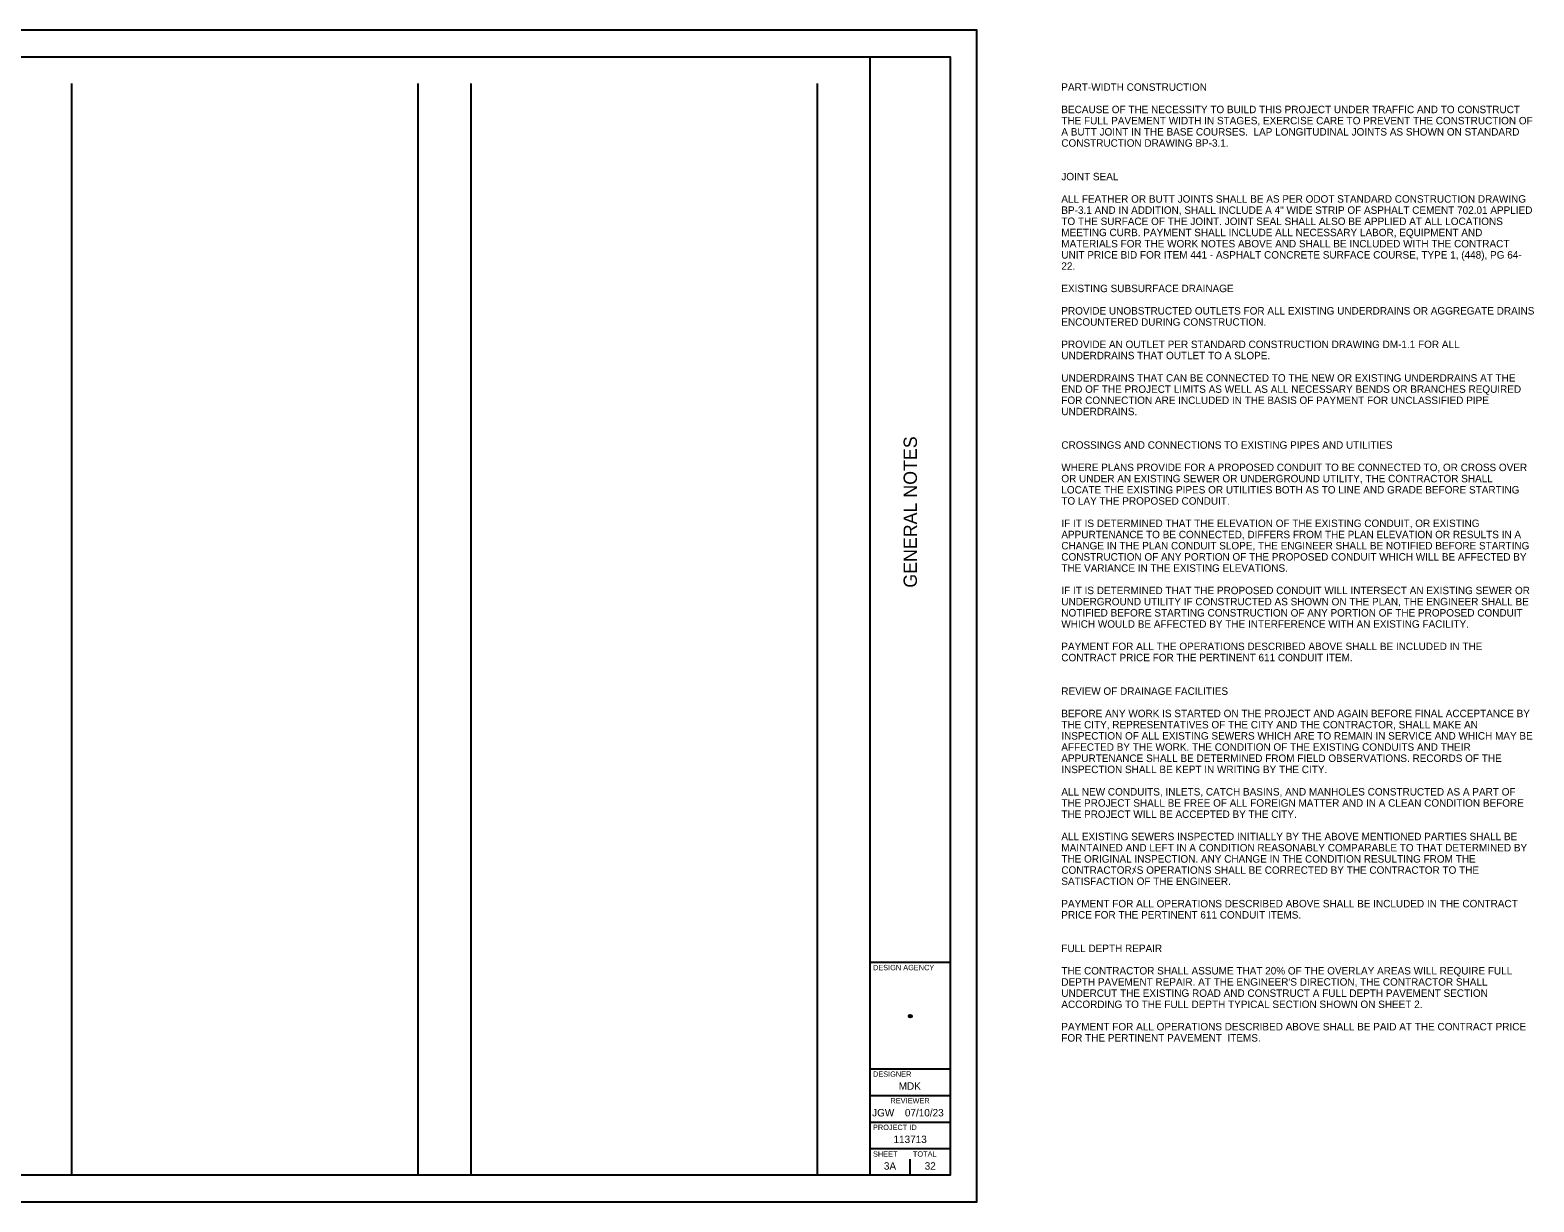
# Model space of a CAD drawing. Extents: x -8.5 to 44.5, y -30.9 to 22.
# Drawn here: x 16.22 to 44.46, y 0 to 22 of the extents above; entities that cross this region are included whole.
import ezdxf

# ---------------------------------------------------------------- set-up
doc = ezdxf.new("R2010")
doc.units = 0
for name, color, linetype in [('Default', 7, 'Continuous'), ('SN_X_Public', 7, 'Continuous'), ('SV_P_Mon_Cells_Set', 7, 'Continuous'), ('SV_X_Mon_Cells_Found', 7, 'Continuous'), ('SV_X_Random_Point', 7, 'Continuous'), ('SV_X_Shot_Marker', 7, 'Continuous')]:
    doc.layers.add(name, color=color, linetype=linetype)

msp = doc.modelspace()

# ---------------------------------------------------------------- linework, layer by layer
at = {"layer": 'Default'}
for p, q in [((32.724, 3.488), (32.776, 3.488)), ((32.75, 3.488), (32.799, 3.488))]:
    msp.add_line(p, q, dxfattribs=at)
msp.add_circle((32.75, 3.488), 0.026, dxfattribs=at)
at = {"layer": 'SN_X_Public'}
for p, q in [((17, 21), (17, 0.5)), ((23.5, 21), (23.5, 0.5)), ((24.5, 21), (24.5, 0.5)), ((31, 21), (31, 0.5))]:
    msp.add_line(p, q, dxfattribs=at)
at = {"layer": 'SV_P_Mon_Cells_Set'}
msp.add_lwpolyline([(0, 0), (34, 0), (34, 22), (0, 22)], close=True, dxfattribs=at)
at = {"layer": 'SV_X_Mon_Cells_Found'}
for p, q in [((32, 0.5), (32, 21.5)), ((32, 4.5), (33.5, 4.5)), ((32, 2.5), (33.5, 2.5)), ((32, 2), (33.5, 2)), ((32, 1.5), (33.5, 1.5)), ((32, 1), (33.5, 1))]:
    msp.add_line(p, q, dxfattribs=at)
msp.add_lwpolyline([(1.5, 21.5), (33.5, 21.5), (33.5, 0.5), (1.5, 0.5)], close=True, dxfattribs=at)
at = {"layer": 'SV_X_Shot_Marker'}
for p, q in [((32.75, 3.5), (32.75, 3.5)), ((32.375, 0.675), (32.375, 0.675)), ((32.75, 0.5), (32.75, 0.8))]:
    msp.add_line(p, q, dxfattribs=at)

# ---------------------------------------------------------------- texts
at = {"layer": 'Default'}
for s, p in [('3A', (32.747, 3.478)), ('1', (32.749, 3.495)), ('Drawing', (32.782, 3.495)), ('1:1', (32.782, 3.478))]:
    msp.add_text(s, height=0.00328, dxfattribs=at).set_placement(p)
at = {"layer": 'SV_X_Random_Point'}
for s, p in [('PART-WIDTH CONSTRUCTION', (35.587, 20.86)), ('THE FULL PAVEMENT WIDTH IN STAGES, EXERCISE CARE TO PREVENT THE CONSTRUCTION OF ', (35.587, 20.23)), ('BECAUSE OF THE NECESSITY TO BUILD THIS PROJECT UNDER TRAFFIC AND TO CONSTRUCT ', (35.587, 20.44)), ('A BUTT JOINT IN THE BASE COURSES.  LAP LONGITUDINAL JOINTS AS SHOWN ON STANDARD ', (35.587, 20.02)), ('CONSTRUCTION DRAWING BP-3.1.', (35.587, 19.81)), ('JOINT SEAL', (35.587, 19.18)), ('ALL FEATHER OR BUTT JOINTS SHALL BE AS PER ODOT STANDARD CONSTRUCTION DRAWING ', (35.587, 18.76)), ('BP-3.1 AND IN ADDITION, SHALL INCLUDE A 4" WIDE STRIP OF ASPHALT CEMENT 702.01 APPLIED ', (35.587, 18.55)), ('TO THE SURFACE OF THE JOINT. JOINT SEAL SHALL ALSO BE APPLIED AT ALL LOCATIONS ', (35.587, 18.34)), ('MEETING CURB. PAYMENT SHALL INCLUDE ALL NECESSARY LABOR, EQUIPMENT AND ', (35.587, 18.13)), ('UNIT PRICE BID FOR ITEM 441 - ASPHALT CONCRETE SURFACE COURSE, TYPE 1, (448), PG 64-', (35.587, 17.71)), ('MATERIALS FOR THE WORK NOTES ABOVE AND SHALL BE INCLUDED WITH THE CONTRACT ', (35.587, 17.92)), ('22.', (35.587, 17.5)), ('EXISTING SUBSURFACE DRAINAGE', (35.587, 17.08)), ('PROVIDE UNOBSTRUCTED OUTLETS FOR ALL EXISTING UNDERDRAINS OR AGGREGATE DRAINS ', (35.587, 16.66)), ('ENCOUNTERED DURING CONSTRUCTION.', (35.587, 16.45)), ('PROVIDE AN OUTLET PER STANDARD CONSTRUCTION DRAWING DM-1.1 FOR ALL ', (35.587, 16.03)), ('UNDERDRAINS THAT OUTLET TO A SLOPE.', (35.587, 15.82)), ('UNDERDRAINS THAT CAN BE CONNECTED TO THE NEW OR EXISTING UNDERDRAINS AT THE ', (35.587, 15.4)), ('END OF THE PROJECT LIMITS AS WELL AS ALL NECESSARY BENDS OR BRANCHES REQUIRED ', (35.587, 15.19)), ('FOR CONNECTION ARE INCLUDED IN THE BASIS OF PAYMENT FOR UNCLASSIFIED PIPE ', (35.587, 14.98)), ('UNDERDRAINS.', (35.587, 14.77)), ('CROSSINGS AND CONNECTIONS TO EXISTING PIPES AND UTILITIES', (35.587, 14.14)), ('WHERE PLANS PROVIDE FOR A PROPOSED CONDUIT TO BE CONNECTED TO, OR CROSS OVER ', (35.587, 13.72)), ('OR UNDER AN EXISTING SEWER OR UNDERGROUND UTILITY, THE CONTRACTOR SHALL ', (35.587, 13.51)), ('LOCATE THE EXISTING PIPES OR UTILITIES BOTH AS TO LINE AND GRADE BEFORE STARTING ', (35.587, 13.3)), ('TO LAY THE PROPOSED CONDUIT.', (35.587, 13.09)), ('IF IT IS DETERMINED THAT THE ELEVATION OF THE EXISTING CONDUIT, OR EXISTING ', (35.587, 12.67)), ('APPURTENANCE TO BE CONNECTED, DIFFERS FROM THE PLAN ELEVATION OR RESULTS IN A ', (35.587, 12.46)), ('CHANGE IN THE PLAN CONDUIT SLOPE, THE ENGINEER SHALL BE NOTIFIED BEFORE STARTING ', (35.587, 12.25)), ('CONSTRUCTION OF ANY PORTION OF THE PROPOSED CONDUIT WHICH WILL BE AFFECTED BY ', (35.587, 12.04)), ('THE VARIANCE IN THE EXISTING ELEVATIONS.', (35.587, 11.83)), ('UNDERGROUND UTILITY IF CONSTRUCTED AS SHOWN ON THE PLAN, THE ENGINEER SHALL BE ', (35.587, 11.2)), ('IF IT IS DETERMINED THAT THE PROPOSED CONDUIT WILL INTERSECT AN EXISTING SEWER OR ', (35.587, 11.41)), ('NOTIFIED BEFORE STARTING CONSTRUCTION OF ANY PORTION OF THE PROPOSED CONDUIT ', (35.587, 10.99)), ('WHICH WOULD BE AFFECTED BY THE INTERFERENCE WITH AN EXISTING FACILITY.', (35.587, 10.78)), ('PAYMENT FOR ALL THE OPERATIONS DESCRIBED ABOVE SHALL BE INCLUDED IN THE ', (35.587, 10.36)), ('CONTRACT PRICE FOR THE PERTINENT 611 CONDUIT ITEM.', (35.587, 10.15)), ('REVIEW OF DRAINAGE FACILITIES', (35.587, 9.52)), ('BEFORE ANY WORK IS STARTED ON THE PROJECT AND AGAIN BEFORE FINAL ACCEPTANCE BY ', (35.587, 9.1)), ('THE CITY, REPRESENTATIVES OF THE CITY AND THE CONTRACTOR, SHALL MAKE AN ', (35.587, 8.89)), ('INSPECTION OF ALL EXISTING SEWERS WHICH ARE TO REMAIN IN SERVICE AND WHICH MAY BE ', (35.587, 8.68)), ('AFFECTED BY THE WORK. THE CONDITION OF THE EXISTING CONDUITS AND THEIR ', (35.587, 8.47)), ('APPURTENANCE SHALL BE DETERMINED FROM FIELD OBSERVATIONS. RECORDS OF THE ', (35.587, 8.26)), ('INSPECTION SHALL BE KEPT IN WRITING BY THE CITY.', (35.587, 8.05)), ('ALL NEW CONDUITS, INLETS, CATCH BASINS, AND MANHOLES CONSTRUCTED AS A PART OF ', (35.587, 7.63)), ('THE PROJECT SHALL BE FREE OF ALL FOREIGN MATTER AND IN A CLEAN CONDITION BEFORE ', (35.587, 7.42)), ('THE PROJECT WILL BE ACCEPTED BY THE CITY.', (35.587, 7.21)), ('ALL EXISTING SEWERS INSPECTED INITIALLY BY THE ABOVE MENTIONED PARTIES SHALL BE ', (35.587, 6.79)), ('THE ORIGINAL INSPECTION. ANY CHANGE IN THE CONDITION RESULTING FROM THE ', (35.587, 6.37)), ('MAINTAINED AND LEFT IN A CONDITION REASONABLY COMPARABLE TO THAT DETERMINED BY ', (35.587, 6.58)), ('CONTRACTORﾒS OPERATIONS SHALL BE CORRECTED BY THE CONTRACTOR TO THE ', (35.587, 6.16)), ('SATISFACTION OF THE ENGINEER.', (35.587, 5.95)), ('PAYMENT FOR ALL OPERATIONS DESCRIBED ABOVE SHALL BE INCLUDED IN THE CONTRACT ', (35.587, 5.53)), ('PRICE FOR THE PERTINENT 611 CONDUIT ITEMS.', (35.587, 5.32)), ('FULL DEPTH REPAIR', (35.587, 4.69)), ('THE CONTRACTOR SHALL ASSUME THAT 20% OF THE OVERLAY AREAS WILL REQUIRE FULL ', (35.587, 4.27)), ('UNDERCUT THE EXISTING ROAD AND CONSTRUCT A FULL DEPTH PAVEMENT SECTION ', (35.587, 3.85)), ("DEPTH PAVEMENT REPAIR. AT THE ENGINEER'S DIRECTION, THE CONTRACTOR SHALL ", (35.587, 4.06)), ('ACCORDING TO THE FULL DEPTH TYPICAL SECTION SHOWN ON SHEET 2.', (35.587, 3.64)), ('PAYMENT FOR ALL OPERATIONS DESCRIBED ABOVE SHALL BE PAID AT THE CONTRACT PRICE ', (35.587, 3.22)), ('FOR THE PERTINENT PAVEMENT  ITEMS.', (35.587, 3.01))]:
    msp.add_text(s, height=0.14, dxfattribs=at).set_placement(p)
at = {"layer": 'SV_X_Shot_Marker'}
msp.add_text('GENERAL NOTES', height=0.25, rotation=90, dxfattribs=at).set_placement((32.875, 11.531))
for s, height, p in [('DESIGN AGENCY', 0.1, (32.05, 4.35)), ('DESIGNER', 0.1, (32.05, 2.35)), ('MDK', 0.14, (32.533, 2.105)), ('JGW', 0.14, (32.034, 1.605)), ('REVIEWER', 0.1, (32.378, 1.85)), ('07/10/23', 0.14, (32.649, 1.605)), ('PROJECT ID', 0.1, (32.05, 1.35)), ('113713', 0.14, (32.435, 1.105)), ('SHEET', 0.1, (32.05, 0.85)), ('TOTAL', 0.1, (32.8, 0.85)), ('3A', 0.14, (32.255, 0.605)), ('32', 0.14, (33.021, 0.605))]:
    msp.add_text(s, height=height, dxfattribs=at).set_placement(p)

doc.saveas('drawing.dxf')
